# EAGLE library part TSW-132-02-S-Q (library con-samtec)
THROUGH-HOLE .025" SQ POST HEADER Source: Samtec TSW.pdf
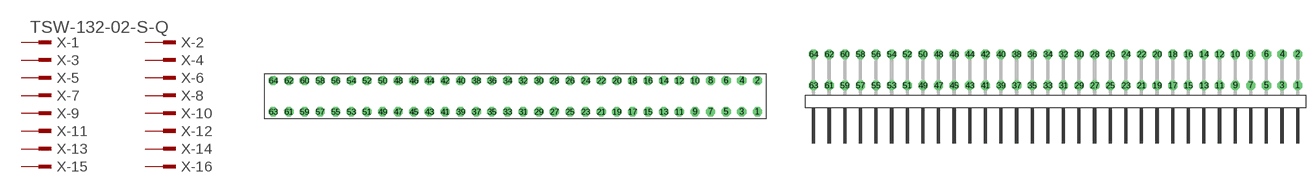
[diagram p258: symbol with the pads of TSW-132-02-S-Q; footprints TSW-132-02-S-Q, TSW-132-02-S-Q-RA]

Designator prefix X; gates -1=MPINV -2=MPIN -3=MPIN -4=MPIN -5=MPIN -6=MPIN -7=MPIN -8=MPIN -9=MPIN -10=MPIN -11=MPIN -12=MPIN -13=MPIN -14=MPIN -15=MPIN -16=MPIN -17=MPIN -18=MPIN -19=MPIN -20=MPIN -21=MPIN -22=MPIN -23=MPIN -24=MPIN -25=MPIN -26=MPIN -27=MPIN -28=MPIN -29=MPIN -30=MPIN -31=MPIN -32=MPIN -33=MPIN -34=MPIN -35=MPIN -36=MPIN -37=MPIN -38=MPIN -39=MPIN -40=MPIN -41=MPIN -42=MPIN -43=MPIN -44=MPIN -45=MPIN -46=MPIN -47=MPIN -48=MPIN -49=MPIN -50=MPIN -51=MPIN -52=MPIN -53=MPIN -54=MPIN -55=MPIN -56=MPIN -57=MPIN -58=MPIN -59=MPIN -60=MPIN -61=MPIN -62=MPIN -63=MPIN -64=MPIN

## TSW-132-02-S-Q (OC_FARNELL: unknown; OC_NEWARK: unknown)  [TSW-132-02-S-Q]
1  -1:1  pas
2  -2:1  pas
3  -3:1  pas
4  -4:1  pas
5  -5:1  pas
6  -6:1  pas
7  -7:1  pas
8  -8:1  pas
9  -9:1  pas
10  -10:1  pas
11  -11:1  pas
12  -12:1  pas
13  -13:1  pas
14  -14:1  pas
15  -15:1  pas
16  -16:1  pas
17  -17:1  pas
18  -18:1  pas
19  -19:1  pas
20  -20:1  pas
21  -21:1  pas
22  -22:1  pas
23  -23:1  pas
24  -24:1  pas
25  -25:1  pas
26  -26:1  pas
27  -27:1  pas
28  -28:1  pas
29  -29:1  pas
30  -30:1  pas
31  -31:1  pas
32  -32:1  pas
33  -33:1  pas
34  -34:1  pas
35  -35:1  pas
36  -36:1  pas
37  -37:1  pas
38  -38:1  pas
39  -39:1  pas
40  -40:1  pas
41  -41:1  pas
42  -42:1  pas
43  -43:1  pas
44  -44:1  pas
45  -45:1  pas
46  -46:1  pas
47  -47:1  pas
48  -48:1  pas
49  -49:1  pas
50  -50:1  pas
51  -51:1  pas
52  -52:1  pas
53  -53:1  pas
54  -54:1  pas
55  -55:1  pas
56  -56:1  pas
57  -57:1  pas
58  -58:1  pas
59  -59:1  pas
60  -60:1  pas
61  -61:1  pas
62  -62:1  pas
63  -63:1  pas
64  -64:1  pas

## TSW-132-02-S-Q-RA (OC_FARNELL: unknown; OC_NEWARK: unknown)  [TSW-132-02-S-Q-RA]
Pads as for TSW-132-02-S-Q

## Footprint TSW-132-02-S-Q (pad centres in mm)
THROUGH-HOLE .025" SQ POST HEADER Source: Samtec TSW.pdf
drill 1 pad 1.5 octagon: 1 39.37,-2.54; 2 39.37,2.54; 3 36.83,-2.54; 4 36.83,2.54; 5 34.29,-2.54; 6 34.29,2.54; 7 31.75,-2.54; 8 31.75,2.54; 9 29.21,-2.54; 10 29.21,2.54; 11 26.67,-2.54; 12 26.67,2.54; 13 24.13,-2.54; 14 24.13,2.54; 15 21.59,-2.54; 16 21.59,2.54; 17 19.05,-2.54; 18 19.05,2.54; 19 16.51,-2.54; 20 16.51,2.54; 21 13.97,-2.54; 22 13.97,2.54; 23 11.43,-2.54; 24 11.43,2.54; 25 8.89,-2.54; 26 8.89,2.54; 27 6.35,-2.54; 28 6.35,2.54; 29 3.81,-2.54; 30 3.81,2.54; 31 1.27,-2.54; 32 1.27,2.54; 33 -1.27,-2.54; 34 -1.27,2.54; 35 -3.81,-2.54; 36 -3.81,2.54; 37 -6.35,-2.54; 38 -6.35,2.54; 39 -8.89,-2.54; 40 -8.89,2.54; 41 -11.43,-2.54; 42 -11.43,2.54; 43 -13.97,-2.54; 44 -13.97,2.54; 45 -16.51,-2.54; 46 -16.51,2.54; 47 -19.05,-2.54; 48 -19.05,2.54; 49 -21.59,-2.54; 50 -21.59,2.54; 51 -24.13,-2.54; 52 -24.13,2.54; 53 -26.67,-2.54; 54 -26.67,2.54; 55 -29.21,-2.54; 56 -29.21,2.54; 57 -31.75,-2.54; 58 -31.75,2.54; 59 -34.29,-2.54; 60 -34.29,2.54; 61 -36.83,-2.54; 62 -36.83,2.54; 63 -39.37,-2.54; 64 -39.37,2.54

## Footprint TSW-132-02-S-Q-RA (pad centres in mm)
THROUGH-HOLE .025" SQ POST HEADER Source: Samtec TSW.pdf
drill 1 pad 1.5 octagon: 1 39.37,1.524; 2 39.37,6.604; 3 36.83,1.524; 4 36.83,6.604; 5 34.29,1.524; 6 34.29,6.604; 7 31.75,1.524; 8 31.75,6.604; 9 29.21,1.524; 10 29.21,6.604; 11 26.67,1.524; 12 26.67,6.604; 13 24.13,1.524; 14 24.13,6.604; 15 21.59,1.524; 16 21.59,6.604; 17 19.05,1.524; 18 19.05,6.604; 19 16.51,1.524; 20 16.51,6.604; 21 13.97,1.524; 22 13.97,6.604; 23 11.43,1.524; 24 11.43,6.604; 25 8.89,1.524; 26 8.89,6.604; 27 6.35,1.524; 28 6.35,6.604; 29 3.81,1.524; 30 3.81,6.604; 31 1.27,1.524; 32 1.27,6.604; 33 -1.27,1.524; 34 -1.27,6.604; 35 -3.81,1.524; 36 -3.81,6.604; 37 -6.35,1.524; 38 -6.35,6.604; 39 -8.89,1.524; 40 -8.89,6.604; 41 -11.43,1.524; 42 -11.43,6.604; 43 -13.97,1.524; 44 -13.97,6.604; 45 -16.51,1.524; 46 -16.51,6.604; 47 -19.05,1.524; 48 -19.05,6.604; 49 -21.59,1.524; 50 -21.59,6.604; 51 -24.13,1.524; 52 -24.13,6.604; 53 -26.67,1.524; 54 -26.67,6.604; 55 -29.21,1.524; 56 -29.21,6.604; 57 -31.75,1.524; 58 -31.75,6.604; 59 -34.29,1.524; 60 -34.29,6.604; 61 -36.83,1.524; 62 -36.83,6.604; 63 -39.37,1.524; 64 -39.37,6.604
